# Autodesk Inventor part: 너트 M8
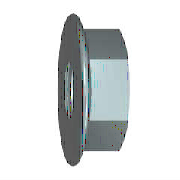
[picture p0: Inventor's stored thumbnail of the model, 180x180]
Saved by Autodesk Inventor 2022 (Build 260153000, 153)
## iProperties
Created: 2015-09
Part Number: 너트 M8
Material: 스테인리스강
Description: 플랜지붙이 6각 너트 - 일반 스레드
Document SubType Name: Modeling
Standard: ISO 4161
Designer: mduedu
Standard Revision: 2판 1999-03-15
Standards Organization: ISO
Language: ko-KR
Size Designation: M8
Categories: <MemberInstance><Categories><Category DisplayName="조임쇠" InternalName="e4da775c-781d-43d5-af7c-5136215cf5a6" Mnemonic="FSTN"><Category DisplayName="너트" InternalN
Density: 8.08 g/cm^3
Appearance: 강철
Author: mduedu
IsCustomPart: 1
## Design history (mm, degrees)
sketch "스케치1"
  geometry: L1 (-1.844, 0)-(9.641, 0) reference; L2 (3.107, 6.5)-(2.288, 8.257); L3 (3.107, 6.5)-(8, 6.5); L4 (8, 6.5)-(8, 0); L5 (3.107, 6.5)-(3.107, 0); L6 (0, -1.835)-(0, 11.01) reference; A1 r 1.2 centre (1.2, 7.75) between (2.288, 8.257) and (0, 7.75); 1 further point
  constraints: 8 end point, 3 point on line, 2 perpendicular, 2 point on circle, 2 tangent, 1 centre point, 1 parallel
  dimensions: "d2" = 13 diameter of L3 L1 (= SW); "d4" = 17.9 dimension on A1 L1 (= LADI); "d5" = 1.2 radius of A1 (= PHH); "d15" = 8 distance between parallel lines of L4 L6 (= KOH); "d16" = 25 deg angle of L6 L2 (= KEWI)
revolve "링" sketch "스케치1" stored, may be unused: angle "d8" = 90 deg
sketch "스케치2"
  geometry: L1 (-6.5, -3.753)-(-6.5, 3.753); L2 (-6.5, 3.753)-(0, 7.506); L3 (0, 7.506)-(6.5, 3.753); L4 (6.5, 3.753)-(6.5, -3.753); L5 (6.5, -3.753)-(0, -7.506); L6 (0, -7.506)-(-6.5, -3.753); C1 r 4.9 at (0, 0); C2 r 7.75 at (0, 0) reference; 1 further point
  constraints: 12 end point, 1 centre point, 1 coincident, 1 vertical, 11 other
  dimensions: "d6" = 15.01111 distance of L5.end L2.end (= 1.1547 x SW)
extrude "본체" join sketch "스케치2" distance "d7" = 8 (= KOH); taper "d9" = 0 deg
sketch "스케치3"
  geometry: L1 (2.638, 7.506)-(8, 7.506) reference; L2 (8, 3.753)-(8, 7.506) reference; L3 (0, -7.75)-(0, 7.75) reference; L4 (-1.6, 0)-(9.6, 0) reference; L5 (7.419, 7.506)-(8, 6.5)
  constraints: 2 end point, 2 point on line
  dimensions: "d10" = 30 deg angle of L2 L5 (= ANG1); "d11" = 13 diameter of L5.end L4 (= SW0)
revolve "모따기1" sketch "스케치3" stored, may be unused: angle "d24" = 90 deg
sketch "스케치4"
  geometry: C1 r 7.75 at (0, 0) reference; 1 further point
  constraints: 1 coincident
hole "스레드" sketch "스케치4" at (0, 0) diameter "d25" = 6.647; stored, may be unused: countersink angle "d29" = 82 deg, drill point angle "d31" = 118 deg; dims "d26" = 6, "d27" = 4, "d28" = 2, "d30" = 8
workaxis "Work Axis1"
workplane "Work Plane1"
body "Solid1"
chamfer "모따기2" distance "d12" = 0.67658 (= -0.5 x GD1 + 0.5 x NND); stored, may be unused: angle "d13" = 30 deg, second distance "d46" = 0.67658 (= -0.5 x GD1 + 0.5 x NND)
chamfer "모따기3" distance "d51" = 0.67658 (= -0.5 x GD1 + 0.5 x NND); stored, may be unused: second distance "d52" = 2, angle "d53" = 45 deg
other parameters: "ANG1" = 30 deg [user parameter; used in 1 equation term], "KEWI" = 25 deg [user parameter; used in 1 equation term], "NND" = 8 [user parameter; used in 4 equation terms], "LADI" = 17.9 [user parameter; used in 2 equation terms], "SW" = 13 [user parameter; used in 3 equation terms], "PHH" = 1.2 [user parameter; used in 3 equation terms], "KOH" = 8 (= NND) [user parameter; used in 2 equation terms], "SW0" = 13 [user parameter; used in 1 equation term], "GD1" = 6.64684 (computed from THREADDIA, PTC, TOA) [user parameter; used in 3 equation terms], "d1" = 17.9 (= LADI), "d3" = 1.2 (= PHH), "d45" = 0, "d47" = 0, "d49" = 0, "d54" = 0, "GUL" = 0.67658 (= 0.541266 x PTC) [user parameter], "TPU" = 8 (computed from PTC) [user parameter], "RR" = 1.2 (= PHH) [user parameter], "THREADDIA" = 8 [user parameter; used in 1 equation term], "TOA" = 30 deg [user parameter; used in 1 equation term], "PTC" = 1.25 [user parameter; used in 4 equation terms], "GAL" = 0.67658 (= 0.541266 x PTC) [user parameter], "E0" = 15.015 (= 1.155 x SW) [user parameter]
